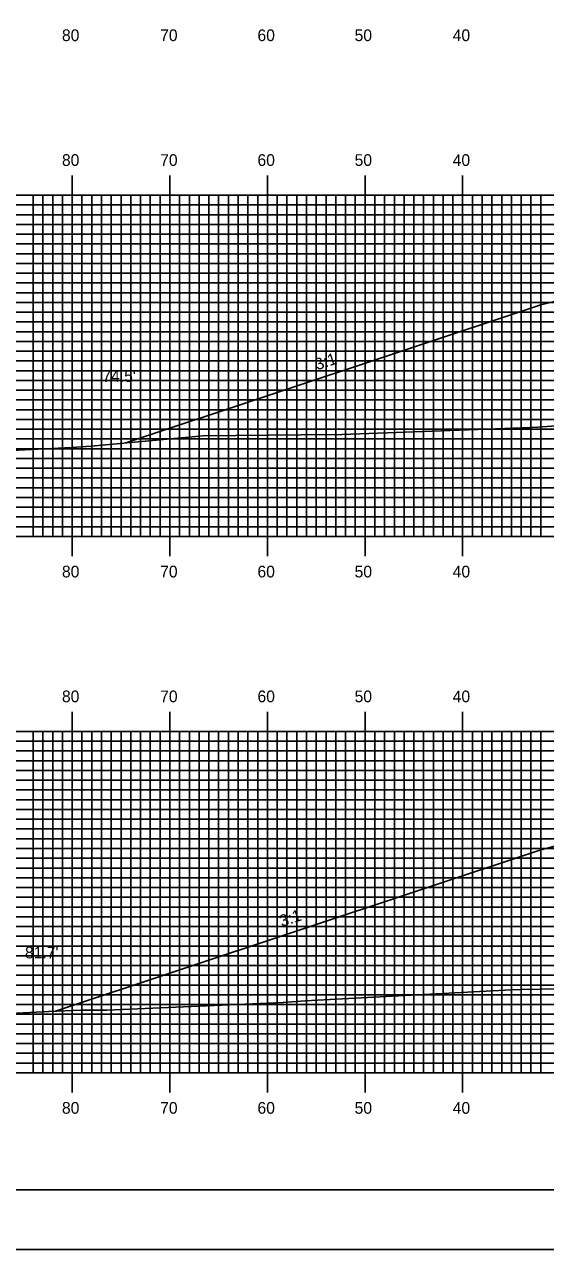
# Model space of a CAD drawing. Extents: x 1782254 to 1782597, y 442591 to 442811.
# Drawn here: x 1782334.5 to 1782387.9, y 442590.5 to 442716.2 of the extents above; entities that cross this region are included whole.
import ezdxf

# ---------------------------------------------------------------- set-up
doc = ezdxf.new("R2010")
doc.units = 0
for name, color, linetype in [('ANNOTATION', 7, 'Continuous'), ('BORDER', 7, 'Continuous'), ('D_Roadway_Centerline', 7, 'Continuous'), ('D_Roadway_SlopeLines', 7, 'Continuous'), ('D_Text_Standard', 7, 'Continuous'), ('H_V ANNOTATION', 7, 'Continuous'), ('MAJOR', 7, 'Continuous'), ('MINOR', 7, 'Continuous'), ('PLOT BOUNDARY', 7, 'Continuous'), ('S_Roadway_Centerline', 7, 'Continuous')]:
    doc.layers.add(name, color=color, linetype=linetype)

msp = doc.modelspace()

# ---------------------------------------------------------------- linework, layer by layer
at = {"layer": 'BORDER'}
msp.add_lwpolyline([(1782269.83, 442596.67), (1782589.83, 442596.67), (1782589.83, 442806.67), (1782269.83, 442806.67)], close=True, dxfattribs=at)
at = {"layer": 'D_Roadway_Centerline'}
for points in [[(1782344.92, 442673.26), (1782387.43, 442687.43), (1782389.26, 442687.88), (1782399.43, 442690.43), (1782407.43, 442690.75), (1782419.43, 442690.99), (1782431.43, 442690.75), (1782439.43, 442690.43), (1782449.61, 442687.88), (1782468.36, 442683.2)], [(1782337.71, 442614.98), (1782387.43, 442631.55), (1782389.26, 442632.01), (1782399.43, 442634.55), (1782407.43, 442634.87), (1782419.43, 442635.11), (1782431.43, 442634.87), (1782439.43, 442634.55), (1782449.61, 442632.01), (1782451.43, 442631.55), (1782482.54, 442621.18)]]:
    msp.add_lwpolyline(points, dxfattribs=at)
at = {"layer": 'D_Roadway_SlopeLines'}
for points in [[(1782399.43, 442690.43), (1782387.43, 442687.43), (1782344.92, 442673.26)], [(1782399.43, 442634.55), (1782387.43, 442631.55), (1782337.71, 442614.98)]]:
    msp.add_lwpolyline(points, dxfattribs=at)
at = {"layer": 'MAJOR'}
for p, q in [((1782339.43, 442700.67), (1782339.43, 442698.67)), ((1782349.43, 442700.67), (1782349.43, 442698.67)), ((1782359.43, 442700.67), (1782359.43, 442698.67)), ((1782369.43, 442700.67), (1782369.43, 442698.67)), ((1782379.43, 442700.67), (1782379.43, 442698.67)), ((1782279.43, 442698.67), (1782559.43, 442698.67)), ((1782279.43, 442698.67), (1782559.43, 442698.67)), ((1782339.43, 442663.67), (1782339.43, 442698.67)), ((1782349.43, 442663.67), (1782349.43, 442698.67)), ((1782359.43, 442663.67), (1782359.43, 442698.67)), ((1782369.43, 442663.67), (1782369.43, 442698.67)), ((1782379.43, 442663.67), (1782379.43, 442698.67)), ((1782279.43, 442693.67), (1782559.43, 442693.67)), ((1782279.43, 442688.67), (1782559.43, 442688.67)), ((1782279.43, 442683.67), (1782559.43, 442683.67)), ((1782279.43, 442678.67), (1782559.43, 442678.67)), ((1782279.43, 442673.67), (1782559.43, 442673.67)), ((1782279.43, 442668.67), (1782559.43, 442668.67)), ((1782279.43, 442663.67), (1782559.43, 442663.67)), ((1782279.43, 442663.67), (1782559.43, 442663.67)), ((1782339.43, 442661.66), (1782339.43, 442663.67)), ((1782349.43, 442661.66), (1782349.43, 442663.67)), ((1782359.43, 442661.66), (1782359.43, 442663.67)), ((1782369.43, 442661.66), (1782369.43, 442663.67)), ((1782379.43, 442661.66), (1782379.43, 442663.67)), ((1782339.43, 442645.67), (1782339.43, 442643.67)), ((1782349.43, 442645.67), (1782349.43, 442643.67)), ((1782359.43, 442645.67), (1782359.43, 442643.67)), ((1782369.43, 442645.67), (1782369.43, 442643.67)), ((1782379.43, 442645.67), (1782379.43, 442643.67)), ((1782279.43, 442643.67), (1782559.43, 442643.67)), ((1782279.43, 442643.67), (1782559.43, 442643.67)), ((1782339.43, 442608.67), (1782339.43, 442643.67)), ((1782349.43, 442608.67), (1782349.43, 442643.67)), ((1782359.43, 442608.67), (1782359.43, 442643.67)), ((1782369.43, 442608.67), (1782369.43, 442643.67)), ((1782379.43, 442608.67), (1782379.43, 442643.67)), ((1782279.43, 442638.67), (1782559.43, 442638.67)), ((1782279.43, 442633.67), (1782559.43, 442633.67)), ((1782279.43, 442628.67), (1782559.43, 442628.67)), ((1782279.43, 442623.67), (1782559.43, 442623.67)), ((1782279.43, 442618.67), (1782559.43, 442618.67)), ((1782279.43, 442613.67), (1782559.43, 442613.67)), ((1782279.43, 442608.67), (1782559.43, 442608.67)), ((1782279.43, 442608.67), (1782559.43, 442608.67)), ((1782339.43, 442606.66), (1782339.43, 442608.67)), ((1782349.43, 442606.66), (1782349.43, 442608.67)), ((1782359.43, 442606.66), (1782359.43, 442608.67)), ((1782369.43, 442606.66), (1782369.43, 442608.67)), ((1782379.43, 442606.66), (1782379.43, 442608.67))]:
    msp.add_line(p, q, dxfattribs=at)
at = {"layer": 'MINOR'}
for p, q in [((1782335.43, 442663.67), (1782335.43, 442698.67)), ((1782336.43, 442663.67), (1782336.43, 442698.67)), ((1782337.43, 442663.67), (1782337.43, 442698.67)), ((1782338.43, 442663.67), (1782338.43, 442698.67)), ((1782340.43, 442663.67), (1782340.43, 442698.67)), ((1782341.43, 442663.67), (1782341.43, 442698.67)), ((1782342.43, 442663.67), (1782342.43, 442698.67)), ((1782343.43, 442663.67), (1782343.43, 442698.67)), ((1782344.43, 442663.67), (1782344.43, 442698.67)), ((1782345.43, 442663.67), (1782345.43, 442698.67)), ((1782346.43, 442663.67), (1782346.43, 442698.67)), ((1782347.43, 442663.67), (1782347.43, 442698.67)), ((1782348.43, 442663.67), (1782348.43, 442698.67)), ((1782350.43, 442663.67), (1782350.43, 442698.67)), ((1782351.43, 442663.67), (1782351.43, 442698.67)), ((1782352.43, 442663.67), (1782352.43, 442698.67)), ((1782353.43, 442663.67), (1782353.43, 442698.67)), ((1782354.43, 442663.67), (1782354.43, 442698.67)), ((1782355.43, 442663.67), (1782355.43, 442698.67)), ((1782356.43, 442663.67), (1782356.43, 442698.67)), ((1782357.43, 442663.67), (1782357.43, 442698.67)), ((1782358.43, 442663.67), (1782358.43, 442698.67)), ((1782360.43, 442663.67), (1782360.43, 442698.67)), ((1782361.43, 442663.67), (1782361.43, 442698.67)), ((1782362.43, 442663.67), (1782362.43, 442698.67)), ((1782363.43, 442663.67), (1782363.43, 442698.67)), ((1782364.43, 442663.67), (1782364.43, 442698.67)), ((1782365.43, 442663.67), (1782365.43, 442698.67)), ((1782366.43, 442663.67), (1782366.43, 442698.67)), ((1782367.43, 442663.67), (1782367.43, 442698.67)), ((1782368.43, 442663.67), (1782368.43, 442698.67)), ((1782370.43, 442663.67), (1782370.43, 442698.67)), ((1782371.43, 442663.67), (1782371.43, 442698.67)), ((1782372.43, 442663.67), (1782372.43, 442698.67)), ((1782373.43, 442663.67), (1782373.43, 442698.67)), ((1782374.43, 442663.67), (1782374.43, 442698.67)), ((1782375.43, 442663.67), (1782375.43, 442698.67)), ((1782376.43, 442663.67), (1782376.43, 442698.67)), ((1782377.43, 442663.67), (1782377.43, 442698.67)), ((1782378.43, 442663.67), (1782378.43, 442698.67)), ((1782380.43, 442663.67), (1782380.43, 442698.67)), ((1782381.43, 442663.67), (1782381.43, 442698.67)), ((1782382.43, 442663.67), (1782382.43, 442698.67)), ((1782383.43, 442663.67), (1782383.43, 442698.67)), ((1782384.43, 442663.67), (1782384.43, 442698.67)), ((1782385.43, 442663.67), (1782385.43, 442698.67)), ((1782386.43, 442663.67), (1782386.43, 442698.67)), ((1782387.43, 442663.67), (1782387.43, 442698.67)), ((1782279.43, 442697.67), (1782559.43, 442697.67)), ((1782279.43, 442696.67), (1782559.43, 442696.67)), ((1782279.43, 442695.67), (1782559.43, 442695.67)), ((1782279.43, 442694.67), (1782559.43, 442694.67)), ((1782279.43, 442692.67), (1782559.43, 442692.67)), ((1782279.43, 442691.67), (1782559.43, 442691.67)), ((1782279.43, 442690.67), (1782559.43, 442690.67)), ((1782279.43, 442689.67), (1782559.43, 442689.67)), ((1782279.43, 442687.67), (1782559.43, 442687.67)), ((1782279.43, 442686.67), (1782559.43, 442686.67)), ((1782279.43, 442685.67), (1782559.43, 442685.67)), ((1782279.43, 442684.67), (1782559.43, 442684.67)), ((1782279.43, 442682.67), (1782559.43, 442682.67)), ((1782279.43, 442681.67), (1782559.43, 442681.67)), ((1782279.43, 442680.67), (1782559.43, 442680.67)), ((1782279.43, 442679.67), (1782559.43, 442679.67)), ((1782279.43, 442677.67), (1782559.43, 442677.67)), ((1782279.43, 442676.67), (1782559.43, 442676.67)), ((1782279.43, 442675.67), (1782559.43, 442675.67)), ((1782279.43, 442674.67), (1782559.43, 442674.67)), ((1782279.43, 442672.67), (1782559.43, 442672.67)), ((1782279.43, 442671.67), (1782559.43, 442671.67)), ((1782279.43, 442670.67), (1782559.43, 442670.67)), ((1782279.43, 442669.67), (1782559.43, 442669.67)), ((1782279.43, 442667.67), (1782559.43, 442667.67)), ((1782279.43, 442666.67), (1782559.43, 442666.67)), ((1782279.43, 442665.67), (1782559.43, 442665.67)), ((1782279.43, 442664.67), (1782559.43, 442664.67)), ((1782335.43, 442608.67), (1782335.43, 442643.67)), ((1782336.43, 442608.67), (1782336.43, 442643.67)), ((1782337.43, 442608.67), (1782337.43, 442643.67)), ((1782338.43, 442608.67), (1782338.43, 442643.67)), ((1782340.43, 442608.67), (1782340.43, 442643.67)), ((1782341.43, 442608.67), (1782341.43, 442643.67)), ((1782342.43, 442608.67), (1782342.43, 442643.67)), ((1782343.43, 442608.67), (1782343.43, 442643.67)), ((1782344.43, 442608.67), (1782344.43, 442643.67)), ((1782345.43, 442608.67), (1782345.43, 442643.67)), ((1782346.43, 442608.67), (1782346.43, 442643.67)), ((1782347.43, 442608.67), (1782347.43, 442643.67)), ((1782348.43, 442608.67), (1782348.43, 442643.67)), ((1782350.43, 442608.67), (1782350.43, 442643.67)), ((1782351.43, 442608.67), (1782351.43, 442643.67)), ((1782352.43, 442608.67), (1782352.43, 442643.67)), ((1782353.43, 442608.67), (1782353.43, 442643.67)), ((1782354.43, 442608.67), (1782354.43, 442643.67)), ((1782355.43, 442608.67), (1782355.43, 442643.67)), ((1782356.43, 442608.67), (1782356.43, 442643.67)), ((1782357.43, 442608.67), (1782357.43, 442643.67)), ((1782358.43, 442608.67), (1782358.43, 442643.67)), ((1782360.43, 442608.67), (1782360.43, 442643.67)), ((1782361.43, 442608.67), (1782361.43, 442643.67)), ((1782362.43, 442608.67), (1782362.43, 442643.67)), ((1782363.43, 442608.67), (1782363.43, 442643.67)), ((1782364.43, 442608.67), (1782364.43, 442643.67)), ((1782365.43, 442608.67), (1782365.43, 442643.67)), ((1782366.43, 442608.67), (1782366.43, 442643.67)), ((1782367.43, 442608.67), (1782367.43, 442643.67)), ((1782368.43, 442608.67), (1782368.43, 442643.67)), ((1782370.43, 442608.67), (1782370.43, 442643.67)), ((1782371.43, 442608.67), (1782371.43, 442643.67)), ((1782372.43, 442608.67), (1782372.43, 442643.67)), ((1782373.43, 442608.67), (1782373.43, 442643.67)), ((1782374.43, 442608.67), (1782374.43, 442643.67)), ((1782375.43, 442608.67), (1782375.43, 442643.67)), ((1782376.43, 442608.67), (1782376.43, 442643.67)), ((1782377.43, 442608.67), (1782377.43, 442643.67)), ((1782378.43, 442608.67), (1782378.43, 442643.67)), ((1782380.43, 442608.67), (1782380.43, 442643.67)), ((1782381.43, 442608.67), (1782381.43, 442643.67)), ((1782382.43, 442608.67), (1782382.43, 442643.67)), ((1782383.43, 442608.67), (1782383.43, 442643.67)), ((1782384.43, 442608.67), (1782384.43, 442643.67)), ((1782385.43, 442608.67), (1782385.43, 442643.67)), ((1782386.43, 442608.67), (1782386.43, 442643.67)), ((1782387.43, 442608.67), (1782387.43, 442643.67)), ((1782279.43, 442642.67), (1782559.43, 442642.67)), ((1782279.43, 442641.67), (1782559.43, 442641.67)), ((1782279.43, 442640.67), (1782559.43, 442640.67)), ((1782279.43, 442639.67), (1782559.43, 442639.67)), ((1782279.43, 442637.67), (1782559.43, 442637.67)), ((1782279.43, 442636.67), (1782559.43, 442636.67)), ((1782279.43, 442635.67), (1782559.43, 442635.67)), ((1782279.43, 442634.67), (1782559.43, 442634.67)), ((1782279.43, 442632.67), (1782559.43, 442632.67)), ((1782279.43, 442631.67), (1782559.43, 442631.67)), ((1782279.43, 442630.67), (1782559.43, 442630.67)), ((1782279.43, 442629.67), (1782559.43, 442629.67)), ((1782279.43, 442627.67), (1782559.43, 442627.67)), ((1782279.43, 442626.67), (1782559.43, 442626.67)), ((1782279.43, 442625.67), (1782559.43, 442625.67)), ((1782279.43, 442624.67), (1782559.43, 442624.67)), ((1782279.43, 442622.67), (1782559.43, 442622.67)), ((1782279.43, 442621.67), (1782559.43, 442621.67)), ((1782279.43, 442620.67), (1782559.43, 442620.67)), ((1782279.43, 442619.67), (1782559.43, 442619.67)), ((1782279.43, 442617.67), (1782559.43, 442617.67)), ((1782279.43, 442616.67), (1782559.43, 442616.67)), ((1782279.43, 442615.67), (1782559.43, 442615.67)), ((1782279.43, 442614.67), (1782559.43, 442614.67)), ((1782279.43, 442612.67), (1782559.43, 442612.67)), ((1782279.43, 442611.67), (1782559.43, 442611.67)), ((1782279.43, 442610.67), (1782559.43, 442610.67)), ((1782279.43, 442609.67), (1782559.43, 442609.67))]:
    msp.add_line(p, q, dxfattribs=at)
at = {"layer": 'PLOT BOUNDARY'}
msp.add_lwpolyline([(1782253.65, 442590.55), (1782593.65, 442590.55), (1782593.65, 442810.55), (1782253.65, 442810.55)], close=True, dxfattribs=at)
at = {"layer": 'S_Roadway_Centerline'}
for points in [[(1782331.82, 442672.41), (1782339.36, 442672.79), (1782341.36, 442672.92), (1782352.85, 442674), (1782362.87, 442674.08), (1782367.05, 442674.13), (1782384.65, 442674.78), (1782387.13, 442674.88), (1782389.48, 442675.05), (1782398.62, 442675.62), (1782407.75, 442675.93), (1782410.52, 442676.12), (1782413.5, 442676.56), (1782433.18, 442677.99), (1782437.45, 442678.65), (1782453.26, 442681.01), (1782460.57, 442682.02), (1782474.99, 442684.2)], [(1782327.84, 442614.47), (1782337.05, 442614.95), (1782340.34, 442615.1), (1782342.99, 442615.09), (1782361.04, 442615.89), (1782363.29, 442616.04), (1782384.41, 442617.17), (1782385.37, 442617.22), (1782387.4, 442617.24), (1782397.96, 442617.27), (1782409.59, 442617.72), (1782409.9, 442617.73), (1782410.26, 442617.75), (1782421.79, 442618.39), (1782433.12, 442618.88), (1782445.07, 442619.26), (1782454.58, 442619.72), (1782456.28, 442619.79), (1782465.88, 442620.13), (1782477.35, 442620.52)]]:
    msp.add_lwpolyline(points, dxfattribs=at)

# ---------------------------------------------------------------- texts
at = {"layer": 'ANNOTATION'}
for p in [(1782364.52, 442680.7), (1782360.91, 442623.62)]:
    msp.add_text('3:1', height=1.2, rotation=18.4348, dxfattribs=at).set_placement(p)
at = {"layer": 'D_Text_Standard'}
for s, p in [("74.5'", (1782342.52, 442679.52)), ("81.7'", (1782334.59, 442620.4))]:
    msp.add_text(s, height=1.2, dxfattribs=at).set_placement(p)
at = {"layer": 'H_V ANNOTATION'}
for s, p in [('80', (1782338.38, 442714.47)), ('70', (1782348.44, 442714.47)), ('60', (1782358.41, 442714.47)), ('50', (1782368.36, 442714.47)), ('40', (1782378.41, 442714.47)), ('80', (1782338.38, 442701.67)), ('70', (1782348.44, 442701.67)), ('60', (1782358.41, 442701.67)), ('50', (1782368.36, 442701.67)), ('40', (1782378.41, 442701.67)), ('80', (1782338.38, 442659.47)), ('70', (1782348.44, 442659.47)), ('60', (1782358.41, 442659.47)), ('50', (1782368.36, 442659.47)), ('40', (1782378.41, 442659.47)), ('80', (1782338.38, 442646.67)), ('70', (1782348.44, 442646.67)), ('60', (1782358.41, 442646.67)), ('50', (1782368.36, 442646.67)), ('40', (1782378.41, 442646.67)), ('80', (1782338.38, 442604.47)), ('70', (1782348.44, 442604.47)), ('60', (1782358.41, 442604.47)), ('50', (1782368.36, 442604.47)), ('40', (1782378.41, 442604.47))]:
    msp.add_text(s, height=1.2, dxfattribs=at).set_placement(p)

doc.saveas('drawing.dxf')
